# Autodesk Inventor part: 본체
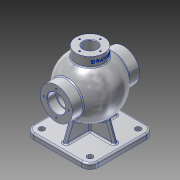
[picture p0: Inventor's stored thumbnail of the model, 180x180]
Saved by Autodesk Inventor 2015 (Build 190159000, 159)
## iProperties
Created: 2025-08
Part Number: 본체
Material: 알루미늄 6061
Document SubType Name: Modeling
Designer: user
Density: 2.7 g/cm^3
Appearance: 알루미늄 - 평지
Mass: 1526.68 g
Surface Area: 1174.39 cm^2
Volume: 565.437 cm^3
Author: user
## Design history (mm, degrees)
sketch "스케치2"
  geometry: L1 (-62.5, -62.5)-(62.5, -62.5); L2 (62.5, -62.5)-(62.5, 62.5); L3 (62.5, 62.5)-(-62.5, 62.5); L4 (-62.5, 62.5)-(-62.5, -62.5); L5 (-62.5, -62.5)-(62.5, 62.5); L6 (62.5, -62.5)-(-62.5, 62.5); 1 further point
  constraints: 12 end point, 2 midpoint, 2 parallel, 1 horizontal, 1 perpendicular
  dimensions: "d0" = 125 distance of L3.end L2.end; "d1" = 125 distance of L2.end L1.end
extrude "돌출1" new body sketch "스케치2" distance "d2" = 10; taper "d3" = 0 deg
sketch "스케치6"
  geometry: L1 (-62.5, 0)-(-62.5, 10) reference; L2 (-62.5, 10)-(62.5, 10) reference; L3 (62.5, 10)-(62.5, 0) reference; L4 (62.5, 0)-(-62.5, 0) reference; L5 (0, 139)-(0, 31); A1 r 54 centre (0, 85) between (0, 139) and (0, 31); 3 further points
  constraints: 2 end point, 2 midpoint, 2 point on circle, 2 vertical alignment, 1 centre point, 1 coincident, 1 vertical
  dimensions: "d11" = 108 diameter of A1; "d12" = 85 distance from line of A1.centre L4
revolve "회전3" sketch "스케치6" stored, may be unused: angle "d13" = 90 deg
node "작업 평면1"
sketch "스케치7"
  geometry: C1 r 27 at (0, 0); 1 further point
  constraints: 1 centre point, 1 coincident
  dimensions: "d15" = 54 diameter of C1
extrude "돌출2" join sketch "스케치7" stored distance "d16" = 10; taper "d17" = 0 deg
sketch "스케치9"
  geometry: L1 (62.5, -62.5)-(-62.5, -62.5) reference; L2 (-62.5, -62.5)-(-62.5, 62.5) reference; L3 (-62.5, 62.5)-(62.5, 62.5) reference; L4 (62.5, 62.5)-(62.5, -62.5) reference; L5 (-4, -50.5)-(4, -50.5); L6 (4, -50.5)-(4, 50.5); L7 (4, 50.5)-(-4, 50.5); L8 (-4, 50.5)-(-4, -50.5); L9 (-4, -50.5)-(4, 50.5); L10 (4, -50.5)-(-4, 50.5); L11 (-50.5, -4)-(50.5, -4); L12 (50.5, -4)-(50.5, 4); L13 (50.5, 4)-(-50.5, 4); L14 (-50.5, 4)-(-50.5, -4); L15 (-50.5, -4)-(50.5, 4); L16 (50.5, -4)-(-50.5, 4); 1 further point
  constraints: 24 end point, 4 midpoint, 4 parallel, 2 horizontal, 2 perpendicular
  dimensions: "d26" = 8 distance of L6.end L7.end; "d27" = 8 distance of L11.end L12.end; "d28" = 12 distance between parallel lines of L12 L4; "d29" = 12 distance between parallel lines of L7 L3
extrude "돌출4" join sketch "스케치9" distance "d30" = 90; taper "d31" = 0 deg
feature "면 기울기1" dims angle "d32" = 20 deg
node "작업 평면2"
sketch "스케치10"
  geometry: L1 (62.5, 0)-(-62.5, 0) reference; C1 r 31 at (0, 85); 2 further points
  constraints: 1 centre point, 1 midpoint, 1 vertical alignment
  dimensions: "d34" = 62 diameter of C1; "d35" = 85 distance from line of C1.centre L1
extrude "돌출5" join sketch "스케치10" distance "d36" = 130; taper "d37" = 0 deg
sketch "스케치11"
  geometry: L1 (-27, 131.765)-(-27, 150) reference; L2 (-27, 150)-(27, 150) reference; L3 (27, 150)-(27, 131.765) reference; L4 (37.385, 46.034)-(50.5, 10) reference; L5 (50.5, 10)-(62.5, 10) reference; L6 (62.5, 10)-(62.5, 0) reference; L7 (62.5, 0)-(-62.5, 0) reference; L8 (-62.5, 0)-(-62.5, 10) reference; L9 (-62.5, 10)-(-50.5, 10) reference; L10 (-50.5, 10)-(-37.385, 46.034) reference; L11 (0, 129)-(0, 41); A1 r 54 centre (0, 85) between (37.385, 46.034) and (27, 131.765) reference; A2 r 54 centre (0, 85) between (-27, 131.765) and (-37.385, 46.034) reference; A3 r 44 centre (0, 85) between (0, 129) and (0, 41); 3 further points
  constraints: 2 coincident, 2 end point, 2 midpoint, 2 point on circle, 1 centre point, 1 vertical, 1 vertical alignment
  dimensions: "d38" = 88 diameter of A3
revolve "회전4" sketch "스케치11" stored, may be unused: angle "d39" = 90 deg
sketch "스케치14"
  geometry: C1 r 27 at (0, 0) reference; C2 r 13 at (0, 0); 1 further point
  constraints: 1 centre point, 1 coincident
  dimensions: "d41" = 26 diameter of C2
extrude "돌출6" cut sketch "스케치14" distance "d42" = 40; taper "d43" = 0 deg
hole "구멍1" diameter "d46" = 30; stored, may be unused: countersink angle "d50" = 90 deg, drill point angle "d52" = 0 deg; dims "d44" = 10, "d45" = 10, "d47" = 12, "d48" = 35, "d49" = 16, "d51" = 30
sketch "스케치19"
  geometry: L1 (0, 0)-(0, 24); C1 r 17.5 at (0, 0) reference; 1 further point
  constraints: 2 end point, 1 vertical
  dimensions: "d54" = 24 distance of L1.start L1.end
hole "구멍2" sketch "스케치19" at (0, 24) diameter "d55" = 3.242; stored, may be unused: countersink angle "d59" = 90 deg, drill point angle "d61" = 118 deg; dims "d56" = 12, "d57" = 35, "d58" = 16, "d60" = 15
sketch "스케치20"
  geometry: L1 (0, 0)-(0, 20)
  constraints: 2 end point, 1 vertical
  dimensions: "d65" = 20 distance of L1.start L1.end
hole "구멍3" sketch "스케치20" at (0, 20) diameter "d66" = 3.242; stored, may be unused: countersink angle "d70" = 90 deg, drill point angle "d72" = 118 deg; dims "d67" = 9, "d68" = 35, "d69" = 16, "d71" = 11
node "작업 평면3"
sketch "스케치21"
  geometry: L1 (-27, 150)-(27, 150) reference; 2 further points
  constraints: 1 vertical alignment, 1 other
  dimensions: "d77" = 9 distance from line of point (0, 141) L1
feature "엠보싱1" sketch "스케치21" dims "d0" = 125, "d1" = 125, "d78" = 0.5, "d79" = 0
fillet "모깎기1" dims "d80" = 3
fillet "모깎기2" dims "d81" = 3
fillet "모깎기3" dims "d82" = 3
fillet "모깎기4" dims "d83" = 16
hole "구멍4" diameter "d86" = 11; stored, may be unused: countersink angle "d90" = 90 deg, drill point angle "d92" = 118 deg; dims "d84" = 10, "d85" = 10, "d87" = 9, "d88" = 35, "d89" = 16, "d91" = 11
hole "구멍5" diameter "d95" = 11; stored, may be unused: countersink angle "d99" = 90 deg, drill point angle "d101" = 118 deg; dims "d93" = 10, "d94" = 10, "d96" = 9, "d97" = 35, "d98" = 16, "d100" = 11
hole "구멍6" diameter "d104" = 11; stored, may be unused: countersink angle "d108" = 90 deg, drill point angle "d110" = 118 deg; dims "d102" = 10, "d103" = 10, "d105" = 9, "d106" = 35, "d107" = 16, "d109" = 11
hole "구멍7" diameter "d113" = 11; stored, may be unused: countersink angle "d117" = 90 deg, drill point angle "d119" = 118 deg; dims "d111" = 10, "d112" = 10, "d114" = 9, "d115" = 35, "d116" = 16, "d118" = 11
fillet "모깎기5" dims "d120" = 3
chamfer "모따기1" distance "d121" = 1; stored, may be unused: second distance "d122" = 2, angle "d123" = 45 deg
node "솔리드1"
mirror "대칭1"
pattern_circular "원형 패턴1" dims angle "d63" = 360 deg
mirror "대칭2"
pattern_circular "원형 패턴2" dims angle "d74" = 360 deg
node "절단 모서리 투영1"
node "절단 모서리 투영3"
node "절단 모서리 투영4"
node "절단 모서리 투영5"
other parameters: "d33" = -65, "d76" = 142.5
